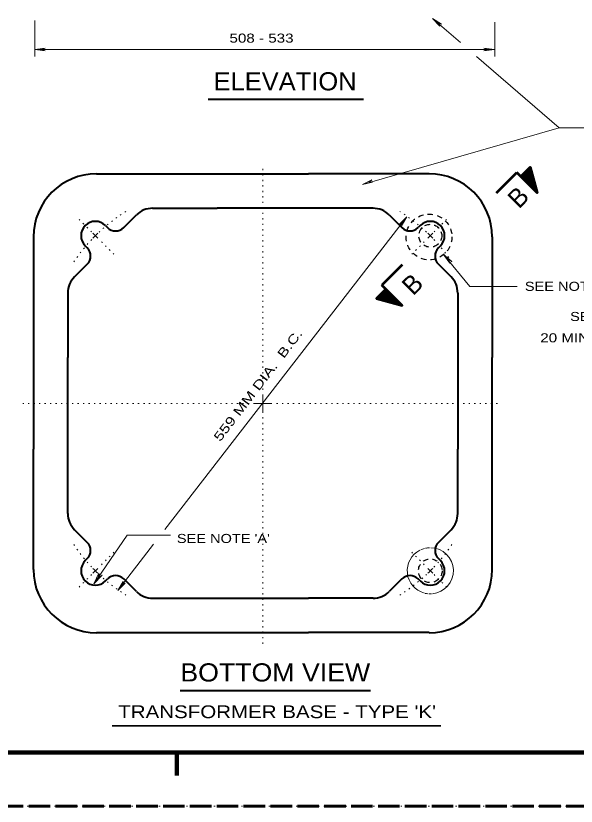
# Model space of a CAD drawing. Extents: x 312583 to 312854, y 144419 to 144597.
# Drawn here: x 312713.9 to 312760.8, y 144418.6 to 144484.7 of the extents above; entities that cross this region are included whole.
import ezdxf
from ezdxf.enums import TextEntityAlignment as Align

# ---------------------------------------------------------------- set-up
doc = ezdxf.new("R2010")
doc.units = 0
doc.header["$LTSCALE"] = 0.3
for name, pattern in [('DOTTED', [1.5, 0.3, -1.2]), ('LONG_DASHED', [7.5, 6, -1.5]), ('SHORT_DASHED', [2.7, 1.5, -1.2])]:
    doc.linetypes.add(name, pattern=pattern)
for name, color, linetype, lineweight in [('1', 7, 'Continuous', 40), ('2', 7, 'Continuous', 13), ('3', 7, 'Continuous', 13), ('62', 7, 'DOTTED', 13), ('63', 7, 'LONG_DASHED', 60)]:
    doc.layers.add(name, color=color, linetype=linetype, lineweight=lineweight)

msp = doc.modelspace()

# ---------------------------------------------------------------- linework, layer by layer
at = {"layer": '1'}
for p, q in [((312720.6364, 144471.5212), (312738.3924, 144471.5212)), ((312730.764, 144471.5212), (312734.5897, 144471.5212)), ((312748.474, 144471.5212), (312738.3924, 144471.5212)), ((312725.3284, 144468.6386), (312730.7257, 144468.6386)), ((312734.5897, 144468.6386), (312730.7257, 144468.6386)), ((312722.9134, 144467.0132), (312723.9714, 144468.0712)), ((312745.1467, 144468.0712), (312746.197, 144467.0132)), ((312721.38, 144467.1819), (312721.5487, 144467.0132)), ((312747.7304, 144467.1819), (312747.5617, 144467.0132)), ((312753.764, 144466.2389), (312753.764, 144456.1496)), ((312719.6857, 144465.4876), (312719.8544, 144465.3189)), ((312749.4324, 144465.4876), (312749.256, 144465.3189)), ((312718.7964, 144462.9039), (312719.8544, 144463.9619)), ((312749.256, 144463.9619), (312750.314, 144462.9039)), ((312718.2367, 144461.5392), (312718.2367, 144456.1496)), ((312715.354, 144438.3936), (312715.354, 144448.4829)), ((312750.8814, 144443.0856), (312750.8814, 144448.4829)), ((312719.8544, 144440.6706), (312718.7964, 144441.7286)), ((312750.314, 144441.7286), (312749.256, 144440.6706)), ((312719.6857, 144439.1372), (312719.8544, 144439.3059)), ((312749.4324, 144439.1372), (312749.256, 144439.3059)), ((312721.38, 144437.4429), (312721.5487, 144437.6116)), ((312723.9714, 144436.5536), (312722.9134, 144437.6116)), ((312746.197, 144437.6116), (312745.1467, 144436.5536)), ((312747.7304, 144437.4429), (312747.5617, 144437.6116)), ((312725.3284, 144435.9862), (312738.3924, 144435.9862)), ((312730.764, 144435.9862), (312734.5897, 144435.9862)), ((312743.782, 144435.9862), (312738.3924, 144435.9862)), ((312720.6364, 144433.1112), (312738.3924, 144433.1112)), ((312730.764, 144433.1112), (312734.5897, 144433.1112)), ((312748.474, 144433.1112), (312738.3924, 144433.1112)), ((312727.6332, 144428.2659), (312743.5814, 144428.2659))]:
    msp.add_line(p, q, dxfattribs=at)
at = {"layer": '1', "linetype": 'DOTTED', "lineweight": 13}
for p, q in [((312720.2147, 144466.6529), (312719.0954, 144467.7722)), ((312748.8957, 144466.6529), (312750.015, 144467.7722)), ((312722.093, 144464.7822), (312720.851, 144466.0242)), ((312747.025, 144464.7822), (312748.267, 144466.0242)), ((312722.093, 144439.8426), (312720.851, 144438.6082)), ((312747.025, 144439.8426), (312748.267, 144438.6082)), ((312720.2147, 144437.9719), (312719.0954, 144436.8526)), ((312748.8957, 144437.9719), (312750.015, 144436.8526))]:
    msp.add_line(p, q, dxfattribs=at)
at = {"layer": '1', "lineweight": 13}
for p, q in [((312720.736, 144466.1316), (312720.3297, 144466.5379)), ((312748.3744, 144466.1316), (312748.7807, 144466.5379)), ((312720.736, 144438.4932), (312720.3297, 144438.0869)), ((312748.3744, 144438.4932), (312748.7807, 144438.0869))]:
    msp.add_line(p, q, dxfattribs=at)
at = {"layer": '1', "lineweight": 35}
msp.add_line((312721.9498, 144425.2989), (312749.464, 144425.2989), dxfattribs=at)
at = {"layer": '1', "lineweight": 158}
for p, q in [((312616.5, 144423.0846), (312849, 144423.0846)), ((312727.35, 144421.1646), (312727.35, 144423.0846))]:
    msp.add_line(p, q, dxfattribs=at)
at = {"layer": '1'}
for points in [[(312743.782, 144468.6386), (312738.3924, 144468.6386), (312730.764, 144468.6386)], [(312715.354, 144466.2312), (312715.354, 144452.3162), (312715.354, 144448.4829)], [(312750.8814, 144461.5392), (312750.8814, 144452.3162), (312750.8814, 144448.4829)], [(312718.2367, 144443.0856), (312718.2367, 144452.3162), (312718.2367, 144456.1496)], [(312753.764, 144438.3936), (312753.764, 144452.3162), (312753.764, 144456.1496)]]:
    msp.add_lwpolyline(points, dxfattribs=at)
at = {"layer": '1', "linetype": 'SHORT_DASHED', "lineweight": 25}
for centre, radius in [((312748.4759, 144466.2331), 1.9167), ((312748.5775, 144466.3347), 0.9583), ((312748.5784, 144438.2891), 0.9934)]:
    msp.add_circle(centre, radius, dxfattribs=at)
at = {"layer": '1'}
for centre, radius, start, end in [((312720.6337, 144466.2337), 5.2842, 90, 180), ((312748.4765, 144466.2337), 5.2842, 0, 90), ((312725.3265, 144466.7141), 1.9215, 90, 135), ((312743.7837, 144466.7141), 1.9215, 45, 90), ((312720.5319, 144466.3356), 1.201, 45, 225), ((312748.5784, 144466.3356), 1.201, 315, 135), ((312722.2305, 144467.6943), 0.9608, 225, 315), ((312746.8797, 144467.6943), 0.9608, 225, 315), ((312719.1732, 144464.637), 0.9608, 315, 45), ((312749.9371, 144464.637), 0.9608, 135, 225), ((312720.1533, 144461.5409), 1.9215, 135, 180), ((312748.9569, 144461.5409), 1.9215, 0, 45), ((312720.1533, 144443.0838), 1.9215, 180, 225), ((312748.9569, 144443.0838), 1.9215, 315, 0), ((312719.1732, 144439.9878), 0.9608, 315, 45), ((312749.9371, 144439.9878), 0.9608, 135, 225), ((312720.5319, 144438.2891), 1.201, 135, 315), ((312748.5784, 144438.2891), 1.201, 225, 45), ((312720.6337, 144438.391), 5.2842, 180, 270), ((312748.4765, 144438.391), 5.2842, 270, 0), ((312722.2305, 144436.9304), 0.9608, 45, 135), ((312746.8797, 144436.9304), 0.9608, 45, 135), ((312725.3265, 144437.9106), 1.9215, 225, 270), ((312743.7837, 144437.9106), 1.9215, 270, 315)]:
    msp.add_arc(centre, radius, start, end, dxfattribs=at)
at = {"layer": '1', "linetype": 'DOTTED', "lineweight": 13}
for centre, start, end in [((312730.7218, 144456.1457), 121.96733, 133.24434), ((312738.3885, 144456.1457), 46.75566, 58.03267), ((312730.7218, 144456.1457), 136.75599, 146.30781), ((312738.3885, 144456.1457), 33.69219, 43.24401), ((312730.7218, 144448.479), 213.69219, 223.24401), ((312738.3885, 144448.479), 316.75599, 326.30781), ((312730.7218, 144448.479), 226.75566, 238.03268), ((312738.3885, 144448.479), 301.96733, 313.24434)]:
    msp.add_arc(centre, 14.4115, start, end, dxfattribs=at)
at = {"layer": '1', "lineweight": 13}
for centre, radius, start, end in [((312730.7218, 144456.1457), 14.4115, 133.83351, 136.1341), ((312738.3885, 144456.1457), 14.4115, 43.8659, 46.16649), ((312748.5784, 144438.2891), 1.9334, 116.79454, 255.14924), ((312748.5784, 144438.2891), 1.9334, 104.7083, 114.31631), ((312748.5784, 144438.2891), 1.9334, 92.27696, 101.90639), ((312748.5784, 144438.2891), 1.9334, 275.24598, 88.67448), ((312730.7218, 144448.479), 14.4115, 223.8659, 226.16649), ((312738.3885, 144448.479), 14.4115, 313.83351, 316.1341), ((312748.5784, 144438.2891), 1.9334, 257.50819, 264.13093), ((312748.5784, 144438.2891), 1.9334, 266.0607, 272.6285)]:
    msp.add_arc(centre, radius, start, end, dxfattribs=at)
at = {"layer": '2'}
for p, q in [((312715.4537, 144484.3399), (312715.4537, 144481.3422)), ((312748.773, 144484.5162), (312749.3787, 144483.8876)), ((312748.773, 144484.5162), (312749.509, 144484.0486)), ((312751.096, 144482.4999), (312748.773, 144484.5162)), ((312749.3787, 144483.8876), (312749.233, 144484.1406)), ((312749.509, 144484.0486), (312749.233, 144484.1406)), ((312753.9864, 144484.2019), (312753.9864, 144481.3422)), ((312715.4537, 144481.9249), (312716.32, 144482.0322)), ((312716.32, 144482.0322), (312716.044, 144481.9249)), ((312753.074, 144482.0322), (312753.35, 144481.9249)), ((312753.9404, 144481.9249), (312753.074, 144482.0322)), ((312715.4537, 144481.9249), (312753.9404, 144481.9249)), ((312715.4537, 144481.9249), (312716.32, 144481.8176)), ((312716.32, 144481.8176), (312716.044, 144481.9249)), ((312753.074, 144481.8176), (312753.35, 144481.9249)), ((312753.9404, 144481.9249), (312753.074, 144481.8176)), ((312759.376, 144475.3546), (312752.4607, 144481.3269)), ((312759.376, 144475.3546), (312742.908, 144470.6166)), ((312759.376, 144475.3546), (312763.6004, 144475.3546)), ((312742.908, 144470.6166), (312743.6824, 144471.0229)), ((312742.908, 144470.6166), (312743.7514, 144470.8236)), ((312743.6824, 144471.0229), (312743.46, 144470.8236)), ((312743.7514, 144470.8236), (312743.46, 144470.8236)), ((312746.6034, 144467.9179), (312745.99, 144467.2969)), ((312746.6034, 144467.9179), (312746.1587, 144467.1666)), ((312745.99, 144467.2969), (312746.243, 144467.4502)), ((312746.1587, 144467.1666), (312746.243, 144467.4502)), ((312749.693, 144464.7516), (312750.2067, 144464.0462)), ((312749.693, 144464.7516), (312750.3677, 144464.1919)), ((312750.2067, 144464.0462), (312750.0994, 144464.3222)), ((312750.3677, 144464.1919), (312750.0994, 144464.3222)), ((312734.5514, 144452.2856), (312734.5514, 144453.0522)), ((312734.5514, 144452.2856), (312733.7847, 144452.2856)), ((312734.5514, 144452.2856), (312735.318, 144452.2856)), ((312734.5514, 144452.2856), (312734.5514, 144451.5189)), ((312720.414, 144437.2052), (312723.197, 144441.2839)), ((312723.197, 144441.2839), (312726.831, 144441.2839)), ((312722.4074, 144436.6456), (312722.852, 144437.3969)), ((312722.4074, 144436.6456), (312723.0207, 144437.2666)), ((312722.852, 144437.3969), (312722.7677, 144437.1132)), ((312723.0207, 144437.2666), (312722.7677, 144437.1132))]:
    msp.add_line(p, q, dxfattribs=at)
at = {"layer": '2', "lineweight": 40}
msp.add_line((312729.9801, 144477.7563), (312742.997, 144477.7563), dxfattribs=at)
at = {"layer": '2', "linetype": 'DOTTED'}
for p, q in [((312734.5514, 144453.4356), (312734.5514, 144472.1959)), ((312733.4014, 144452.2856), (312714.4494, 144452.2856)), ((312735.7014, 144452.2856), (312754.3774, 144452.2856)), ((312734.5514, 144451.1356), (312734.5514, 144432.1836))]:
    msp.add_line(p, q, dxfattribs=at)
at = {"layer": '2', "lineweight": 53}
for p, q in [((312754.132, 144469.9342), (312755.8264, 144471.6286)), ((312756.1637, 144471.2912), (312755.8264, 144471.6286)), ((312746.22, 144463.8929), (312744.5257, 144462.1986)), ((312744.863, 144461.8612), (312744.5257, 144462.1986))]:
    msp.add_line(p, q, dxfattribs=at)
at = {"layer": '2', "lineweight": 35}
for p, q in [((312756.179, 144471.3066), (312757.0914, 144471.5442)), ((312756.179, 144471.2759), (312757.099, 144471.5212)), ((312756.202, 144471.2529), (312757.1067, 144471.5059)), ((312756.2174, 144471.3449), (312757.076, 144471.5749)), ((312756.2174, 144471.2376), (312757.1144, 144471.4752)), ((312756.2327, 144471.2222), (312757.1144, 144471.4599)), ((312756.248, 144471.3756), (312757.076, 144471.5902)), ((312756.2557, 144471.1992), (312757.122, 144471.4369)), ((312756.2864, 144471.4062), (312757.0684, 144471.6209)), ((312756.317, 144471.4446), (312757.0607, 144471.6439)), ((312756.3554, 144471.4752), (312757.0607, 144471.6669)), ((312756.386, 144471.5059), (312757.053, 144471.6899)), ((312756.4244, 144471.5442), (312757.0454, 144471.7129)), ((312756.455, 144471.5826), (312757.0454, 144471.7359)), ((312756.4857, 144471.6132), (312757.03, 144471.7589)), ((312756.524, 144471.6516), (312757.03, 144471.7819)), ((312756.5547, 144471.6822), (312757.03, 144471.8049)), ((312756.5854, 144471.7129), (312757.0147, 144471.8279)), ((312756.6237, 144471.7512), (312757.0147, 144471.8432)), ((312756.662, 144471.7819), (312756.9994, 144471.8739)), ((312756.6927, 144471.8126), (312756.9994, 144471.8969)), ((312756.7234, 144471.8509), (312756.9917, 144471.9199)), ((312756.7617, 144471.8892), (312756.9764, 144471.9429)), ((312756.7924, 144471.9122), (312756.984, 144471.9659)), ((312756.8307, 144471.9506), (312756.9687, 144471.9812)), ((312756.8614, 144471.9889), (312756.9687, 144472.0119)), ((312756.8997, 144472.0272), (312756.961, 144472.0349)), ((312756.9304, 144472.0579), (312756.9534, 144472.0579)), ((312756.2787, 144471.1916), (312757.1297, 144471.4062)), ((312756.3017, 144471.1686), (312757.1297, 144471.3909)), ((312756.3094, 144471.1456), (312757.145, 144471.3679)), ((312756.3324, 144471.1226), (312757.145, 144471.3372)), ((312756.3554, 144471.0996), (312757.145, 144471.3219)), ((312756.3707, 144471.0842), (312757.1604, 144471.2989)), ((312756.3937, 144471.0612), (312757.168, 144471.2682)), ((312756.4167, 144471.0382), (312757.168, 144471.2452)), ((312756.432, 144471.0229), (312757.1757, 144471.2222)), ((312756.455, 144471.0076), (312757.1834, 144471.1992)), ((312756.478, 144470.9846), (312757.191, 144471.1762)), ((312756.4934, 144470.9616), (312757.191, 144471.1532)), ((312756.5087, 144470.9462), (312757.1987, 144471.1302)), ((312756.524, 144470.9309), (312757.2064, 144471.1072)), ((312756.5547, 144470.9002), (312757.214, 144471.0919)), ((312756.5777, 144470.8849), (312757.2217, 144471.0612)), ((312756.593, 144470.8696), (312757.2294, 144471.0382)), ((312756.6084, 144470.8466), (312757.2294, 144471.0229)), ((312756.6314, 144470.8312), (312757.2524, 144470.9922)), ((312756.6467, 144470.8082), (312757.2524, 144470.9692)), ((312756.662, 144470.7929), (312757.2524, 144470.9386)), ((312756.685, 144470.7699), (312757.26, 144470.9232)), ((312756.708, 144470.7469), (312757.26, 144470.9002)), ((312756.7234, 144470.7316), (312757.2754, 144470.8772)), ((312756.7464, 144470.7086), (312757.2754, 144470.8466)), ((312756.7694, 144470.6856), (312757.283, 144470.8312)), ((312756.7847, 144470.6702), (312757.2907, 144470.8082)), ((312756.8077, 144470.6472), (312757.2984, 144470.7852)), ((312756.8307, 144470.6242), (312757.2984, 144470.7622)), ((312756.846, 144470.6089), (312757.3137, 144470.7392)), ((312756.8614, 144470.5936), (312757.3137, 144470.7162)), ((312756.8844, 144470.5782), (312757.329, 144470.6932)), ((312756.8997, 144470.5476), (312757.329, 144470.6702)), ((312756.9227, 144470.5322), (312757.3367, 144470.6472)), ((312756.9457, 144470.5169), (312757.3444, 144470.6242)), ((312756.961, 144470.4939), (312757.3444, 144470.6012)), ((312756.9764, 144470.4786), (312757.352, 144470.5782)), ((312756.9994, 144470.4556), (312757.3597, 144470.5476)), ((312757.0147, 144470.4402), (312757.3597, 144470.5322)), ((312757.0377, 144470.4172), (312757.375, 144470.5092)), ((312757.0607, 144470.3942), (312757.375, 144470.4786)), ((312757.076, 144470.3789), (312757.3827, 144470.4632)), ((312757.099, 144470.3559), (312757.3904, 144470.4326)), ((312757.1144, 144470.3406), (312757.398, 144470.4172)), ((312757.1374, 144470.3176), (312757.4057, 144470.3866)), ((312757.1604, 144470.2946), (312757.4134, 144470.3636)), ((312757.1757, 144470.2792), (312757.4134, 144470.3406)), ((312757.1987, 144470.2562), (312757.4287, 144470.3252)), ((312757.214, 144470.2409), (312757.4287, 144470.2946)), ((312757.237, 144470.2179), (312757.4287, 144470.2716)), ((312757.26, 144470.2026), (312757.444, 144470.2562)), ((312757.283, 144470.1796), (312757.444, 144470.2256)), ((312757.2984, 144470.1566), (312757.4517, 144470.2026)), ((312757.3214, 144470.1412), (312757.4594, 144470.1796)), ((312757.3367, 144470.1182), (312757.467, 144470.1566)), ((312757.352, 144470.1106), (312757.4747, 144470.1336)), ((312757.375, 144470.0876), (312757.4747, 144470.1106)), ((312757.3904, 144470.0646), (312757.4824, 144470.0876)), ((312757.4134, 144470.0416), (312757.49, 144470.0646)), ((312757.4287, 144470.0262), (312757.4977, 144470.0416)), ((312757.4517, 144470.0032), (312757.5054, 144470.0186)), ((312757.467, 144469.9879), (312757.513, 144469.9956)), ((312757.49, 144469.9649), (312757.513, 144469.9802)), ((312757.513, 144469.9419), (312757.5207, 144469.9572)), ((312744.541, 144461.5392), (312744.3954, 144460.9949)), ((312744.5717, 144461.5699), (312744.4184, 144460.9796)), ((312744.61, 144461.6082), (312744.4414, 144460.9796)), ((312744.6484, 144461.6466), (312744.472, 144460.9796)), ((312744.679, 144461.6772), (312744.495, 144460.9642)), ((312744.7097, 144461.7079), (312744.5104, 144460.9642)), ((312744.7404, 144461.7462), (312744.541, 144460.9642)), ((312744.7864, 144461.7846), (312744.564, 144460.9489)), ((312744.8094, 144461.8076), (312744.587, 144460.9489)), ((312744.8477, 144461.8459), (312744.61, 144460.9336)), ((312744.8784, 144461.8536), (312744.633, 144460.9336)), ((312744.8937, 144461.8306), (312744.656, 144460.9182)), ((312744.9167, 144461.8076), (312744.679, 144460.9182)), ((312744.9397, 144461.7922), (312744.6944, 144460.9106)), ((312744.9627, 144461.7692), (312744.725, 144460.9029)), ((312744.9704, 144461.7462), (312744.748, 144460.8952)), ((312744.9857, 144461.7309), (312744.7634, 144460.8952)), ((312745.0087, 144461.7156), (312744.7864, 144460.8799)), ((312745.0317, 144461.6926), (312744.817, 144460.8722)), ((312745.0547, 144461.6696), (312744.84, 144460.8722)), ((312745.07, 144461.6542), (312744.8554, 144460.8646)), ((312745.093, 144461.6312), (312744.886, 144460.8646)), ((312745.1084, 144461.6082), (312744.909, 144460.8569)), ((312745.1314, 144461.5929), (312744.9244, 144460.8492)), ((312745.1467, 144461.5699), (312744.955, 144460.8416)), ((312745.1697, 144461.5546), (312744.978, 144460.8339)), ((312745.1927, 144461.5392), (312745.001, 144460.8339)), ((312745.208, 144461.5162), (312745.024, 144460.8262)), ((312744.0964, 144461.1022), (312744.0964, 144461.0716)), ((312744.1347, 144461.1329), (312744.1194, 144461.0639)), ((312744.1654, 144461.1636), (312744.1424, 144461.0639)), ((312744.2037, 144461.2019), (312744.1654, 144461.0562)), ((312744.2344, 144461.2326), (312744.1884, 144461.0486)), ((312744.265, 144461.2632), (312744.219, 144461.0486)), ((312744.311, 144461.3016), (312744.2344, 144461.0332)), ((312744.3417, 144461.3399), (312744.265, 144461.0332)), ((312744.3647, 144461.3706), (312744.2804, 144461.0256)), ((312744.403, 144461.4012), (312744.311, 144461.0102)), ((312744.4414, 144461.4396), (312744.3264, 144461.0026)), ((312744.472, 144461.4702), (312744.3494, 144461.0026)), ((312744.5027, 144461.5009), (312744.3724, 144460.9949)), ((312745.231, 144461.5009), (312745.047, 144460.8186)), ((312745.254, 144461.4779), (312745.07, 144460.8109)), ((312745.277, 144461.4549), (312745.093, 144460.8109)), ((312745.2847, 144461.4319), (312745.116, 144460.7956)), ((312745.3154, 144461.4166), (312745.1314, 144460.7956)), ((312745.323, 144461.3936), (312745.162, 144460.7802)), ((312745.346, 144461.3782), (312745.185, 144460.7802)), ((312745.3614, 144461.3629), (312745.2157, 144460.7802)), ((312745.3844, 144461.3399), (312745.231, 144460.7649)), ((312745.4074, 144461.3169), (312745.254, 144460.7649)), ((312745.4227, 144461.3016), (312745.277, 144460.7496)), ((312745.4457, 144461.2786), (312745.3077, 144460.7496)), ((312745.4687, 144461.2556), (312745.323, 144460.7419)), ((312745.484, 144461.2402), (312745.346, 144460.7342)), ((312745.507, 144461.2249), (312745.369, 144460.7266)), ((312745.53, 144461.2019), (312745.392, 144460.7266)), ((312745.5454, 144461.1866), (312745.415, 144460.7189)), ((312745.5607, 144461.1636), (312745.438, 144460.7112)), ((312745.5837, 144461.1406), (312745.461, 144460.7036)), ((312745.599, 144461.1176), (312745.484, 144460.6959)), ((312745.6297, 144461.1022), (312745.5147, 144460.6882)), ((312745.6374, 144461.0869), (312745.5377, 144460.6882)), ((312745.6604, 144461.0639), (312745.553, 144460.6806)), ((312745.6834, 144461.0486), (312745.5837, 144460.6806)), ((312745.6987, 144461.0256), (312745.6067, 144460.6652)), ((312745.7217, 144461.0102), (312745.622, 144460.6652)), ((312745.737, 144460.9872), (312745.6527, 144460.6576)), ((312745.76, 144460.9719), (312745.6757, 144460.6499)), ((312745.783, 144460.9489), (312745.691, 144460.6499)), ((312745.7984, 144460.9259), (312745.7217, 144460.6346)), ((312745.8137, 144460.9106), (312745.737, 144460.6269)), ((312745.8367, 144460.8876), (312745.7677, 144460.6192)), ((312745.8597, 144460.8646), (312745.7907, 144460.6116)), ((312745.875, 144460.8492), (312745.8137, 144460.6116)), ((312745.898, 144460.8262), (312745.8367, 144460.6039)), ((312745.9134, 144460.8109), (312745.8597, 144460.5962)), ((312745.9364, 144460.7879), (312745.8827, 144460.5962)), ((312745.9517, 144460.7726), (312745.898, 144460.5886)), ((312745.9747, 144460.7496), (312745.9287, 144460.5809)), ((312745.9977, 144460.7342), (312745.9517, 144460.5809)), ((312746.013, 144460.7112), (312745.9747, 144460.5732)), ((312746.036, 144460.6959), (312745.9977, 144460.5656)), ((312746.0437, 144460.6729), (312746.0207, 144460.5502)), ((312746.0667, 144460.6499), (312746.0437, 144460.5502)), ((312746.0974, 144460.6346), (312746.0667, 144460.5426)), ((312746.1127, 144460.6116), (312746.0974, 144460.5349)), ((312746.128, 144460.5962), (312746.105, 144460.5272)), ((312746.151, 144460.5732), (312746.1357, 144460.5272)), ((312746.1664, 144460.5579), (312746.1587, 144460.5119)), ((312746.1894, 144460.5349), (312746.174, 144460.5119)), ((312746.2124, 144460.5119), (312746.197, 144460.5042))]:
    msp.add_line(p, q, dxfattribs=at)
at = {"layer": '2', "lineweight": 53}
for points in [[(312756.1637, 144471.2912), (312756.9534, 144472.0809), (312757.5207, 144469.9342)], [(312744.863, 144461.8612), (312744.0734, 144461.0792), (312746.22, 144460.5042)]]:
    msp.add_lwpolyline(points, close=True, dxfattribs=at)
at = {"layer": '2'}
msp.add_lwpolyline([(312749.693, 144464.7516), (312751.901, 144462.0836), (312755.8647, 144462.0836)], dxfattribs=at)
msp.add_lwpolyline([(312720.414, 144437.2052), (312721.0964, 144437.9106), (312720.782, 144437.7419), (312720.828, 144438.0946)], close=True, dxfattribs=at)
at = {"layer": '3'}
for p, q in [((312726.3634, 144441.7592), (312746.6034, 144467.9179)), ((312722.4074, 144436.6456), (312725.405, 144440.5172))]:
    msp.add_line(p, q, dxfattribs=at)
at = {"layer": '62'}
msp.add_lwpolyline([(312601.2, 144418.5846), (312853.5, 144418.5846), (312853.5, 144596.7846)], dxfattribs=at)
at = {"layer": '63'}
msp.add_line((312851.75, 144418.5846), (312583.526, 144418.5846), dxfattribs=at)

# ---------------------------------------------------------------- texts
at = {"layer": '2'}
for s, height, width, p in [('508 - 533 ', 0.76, 1.25, (312731.7617, 144482.4963)), ('ELEVATION', 1.52, 1.05, (312730.427, 144478.5021)), ("SEE NOTE 'E'", 0.76, 1.2, (312756.4963, 144461.7195)), ("SEE NOTE 'D'", 0.76, 1.2, (312760.2865, 144459.1961)), (' 20 MIN.', 0.76, 1.25, (312757.4344, 144457.4109)), ("SEE NOTE 'A'", 0.76, 1.2, (312727.3581, 144440.615)), ('BOTTOM VIEW', 1.52, 1.1, (312727.6477, 144429.0233)), ("TRANSFORMER BASE - TYPE 'K'", 1.07, 1.2, (312722.4491, 144425.9542))]:
    msp.add_text(s, height=height, dxfattribs=dict(at, width=width)).set_placement(p)
for height, p in [(1.54, (312756.4815, 144469.0177)), (1.538, (312747.626, 144461.7339))]:
    msp.add_text('B', height=height, rotation=45, dxfattribs=at).set_placement(p, align=Align.CENTER)
at = {"layer": '2', "width": 1.35}
msp.add_text('559 MM DIA.  B.C.', height=0.76, rotation=52.607, dxfattribs=at).set_placement((312730.9822, 144449.0482))

doc.saveas('drawing.dxf')
